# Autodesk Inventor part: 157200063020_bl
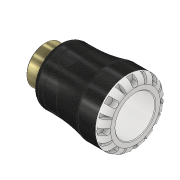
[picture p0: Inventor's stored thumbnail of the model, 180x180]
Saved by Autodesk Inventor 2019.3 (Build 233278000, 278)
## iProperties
Created: 2016-12
Part Number: 157200063020_bl
Material: PVC-Piping
Description: PLASSON  G-PLASS BRASS MALE ADAPTOR 63X2" SERIES 1
Document SubType Name: Modeling
Designer: KIM
Mass: 61.7504 g
Surface Area: 140.097 cm^2
Volume: 44.1074 cm^3
Density: 1.4 g/cm^3
Appearance: Black Cast
Author: KIM
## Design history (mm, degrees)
derived "157200.ipt"
feature "Solid1::157200.ipt" dims "ScaleForDerivedMember" = 10
tag "TaggingFeature1"
body "Solid1"
other parameters: "d0" = 144 [user parameter], "d1" = 40.74 [user parameter], "d2" = 63 [user parameter], "d3" = 78.75 [user parameter], "d4" = 103 [user parameter], "d6" = 97 [user parameter], "d8" = 87.55 [user parameter], "d13" = 9.7 [user parameter], "d14" = 9.7 [user parameter], "d15" = 0 [user parameter], "d17" = 360 deg [user parameter], "d19" = 8 deg [user parameter], "d20" = 1.26 [user parameter], "d21" = 1.26 [user parameter], "d22" = 8 deg [user parameter], "d24" = 0 [user parameter], "d26" = 360 deg [user parameter], "d32" = 10.3 [user parameter], "d33" = 10.3 [user parameter], "d34" = 59.614 [user parameter], "d38" = 23 [user parameter], "d39" = 1.78842 [user parameter], "d42" = 22.05 [user parameter], "d43" = 14.49 [user parameter], "d45" = 19.012 [user parameter], "d46" = 0 [user parameter], "d59" = 360 deg [user parameter], "d61" = 18.7425 [user parameter], "d62" = 1.26 [user parameter], "d64" = 0 [user parameter], "d65" = 1.03 [user parameter], "d68" = 9 [user parameter], "d_" = 63 [user parameter], "E_" = 103 [user parameter], "H_" = 144 [user parameter], "l_" = 97 [user parameter], "R_" = 59.614 [user parameter], "l_2" = 23 [user parameter], "d9" = 12.125 [user parameter], "d11" = 103 [user parameter], "d12" = 78.75 [user parameter]
